Omron Sysmac Studio project sample_fins_test (Sysmac Studio 1.43.0.64009, StandardProject)

# Controller new_Controller_0: NX102-9000 version 1.31
Task PrimaryTask (priority 4, period or condition 2000): Program0

VAR_GLOBAL RETAIN
    FinsData AT %D0 : ARRAY[0..199] OF BYTE;  (* published *)
END_VAR

PROGRAM Program0
VAR RETAIN
    TriggerEnable AT %D0.0 : BOOL;
    Trigger AT %D0.1 : BOOL;
    ResultsAck AT %D0.2 : BOOL;
    ClearError AT %D0.15 : BOOL;
    TriggerReady AT %D1.0 : BOOL;
    TriggerAck AT %D1.1 : BOOL;
    Acquiring AT %D1.2 : BOOL;
    Decoding AT %D1.3 : BOOL;
    ResultsOK AT %D1.8 : BOOL;
    ResultsNG AT %D1.9 : BOOL;
    GeneralFault AT %D1.15 : BOOL;
    ResultLength AT %D2 : UINT;
    ResultData AT %D3 : ARRAY[0..199] OF BYTE;
    ResultDataUser AT %D500 : ARRAY[0..199] OF BYTE;
END_VAR
VAR
    _p1 : BOOL;
    _p2 : BOOL;
    _e3 : R_TRIG;
    _e4 : F_TRIG;
END_VAR

(* Section Section0: ladder, written here as Structured Text *)

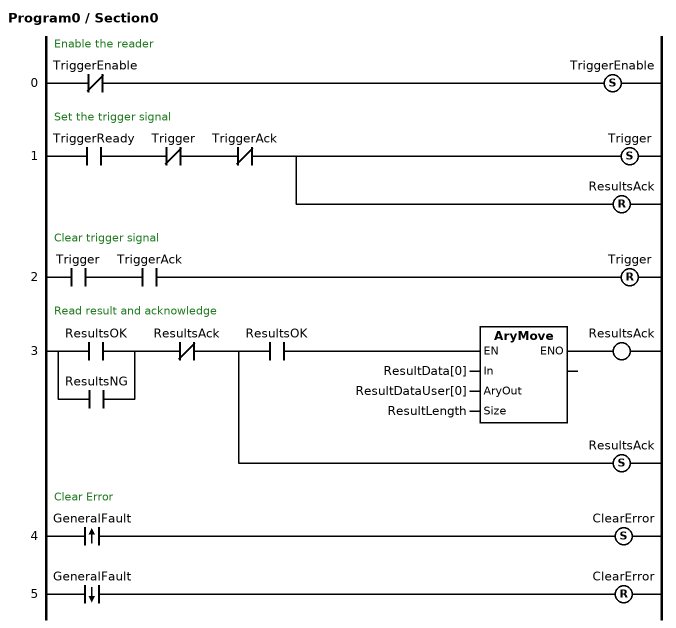
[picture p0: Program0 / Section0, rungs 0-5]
(* Rung 0: Enable the reader *)
IF NOT TriggerEnable THEN TriggerEnable := TRUE; END_IF;
(* Rung 1: Set the trigger signal *)
_p1 := TriggerReady AND NOT Trigger AND NOT TriggerAck;
IF _p1 THEN
    Trigger := TRUE;
    ResultsAck := FALSE;
END_IF;
(* Rung 2: Clear trigger signal *)
IF Trigger AND TriggerAck THEN Trigger := FALSE; END_IF;
(* Rung 3: Read result and acknowledge *)
IF (ResultsOK OR ResultsNG) AND NOT ResultsAck AND ResultsOK THEN
    AryMove(In := ResultData[0], AryOut := ResultDataUser[0], Size := ResultLength);
END_IF;
_p2 := (ResultsOK OR ResultsNG) AND NOT ResultsAck;
ResultsAck := (ResultsOK OR ResultsNG) AND NOT ResultsAck AND ResultsOK;
IF _p2 THEN ResultsAck := TRUE; END_IF;
(* Rung 4: Clear Error *)
_e3(CLK := GeneralFault);
IF _e3.Q THEN ClearError := TRUE; END_IF;
(* Rung 5 *)
_e4(CLK := GeneralFault);
IF _e4.Q THEN ClearError := FALSE; END_IF;
END_PROGRAM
